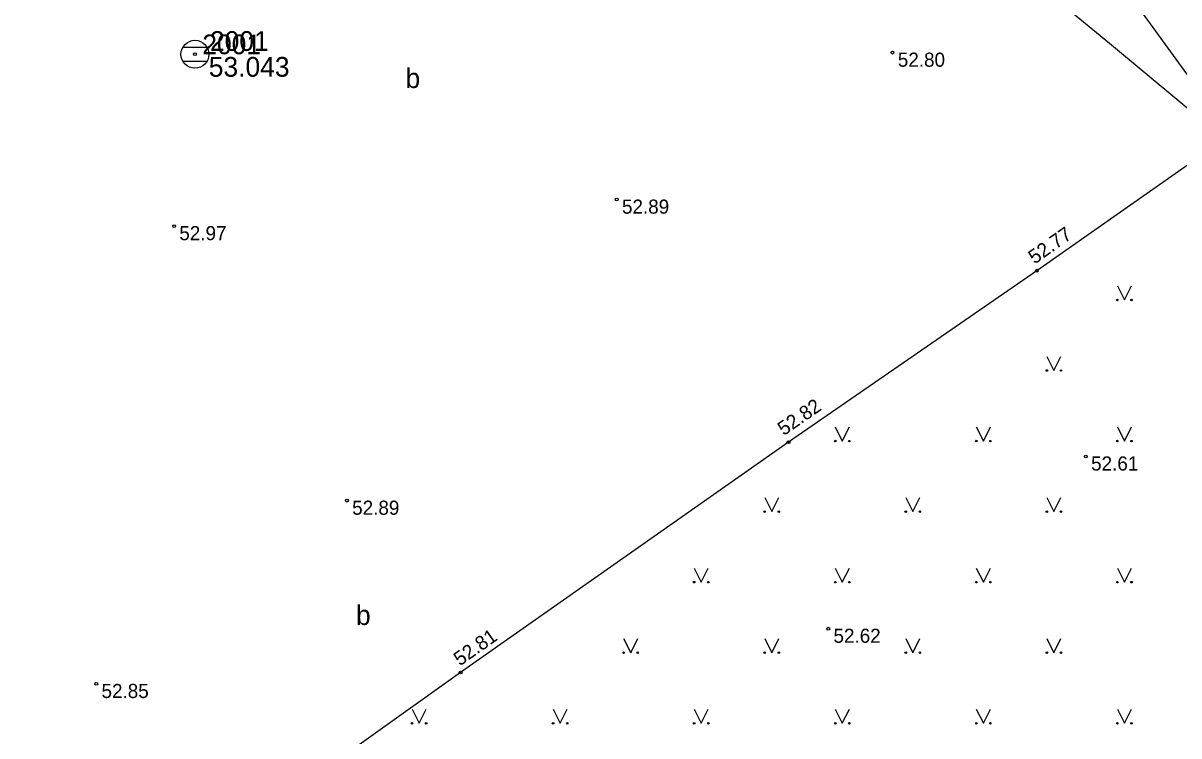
# Model space of a CAD drawing. Extents: x 619806 to 620082, y 405176 to 405386.
# Drawn here: x 619968.46 to 620009.43, y 405267.05 to 405292.31 of the extents above; entities that cross this region are included whole.
import ezdxf

# ---------------------------------------------------------------- set-up
doc = ezdxf.new("R2010")
doc.units = 0
for name, color, linetype in [('CELI_CMAL_####_####_#', 7, 'Continuous'), ('CELI_CSEG_####_TKST_#', 7, 'Continuous'), ('GEOD_ELEM_####_####_#', 7, 'Continuous'), ('GEOD_ELEM_####_TKST_#', 7, 'Continuous'), ('RELJ_AATZ_####_TKST_#', 7, 'Continuous'), ('RELJ_ELEM_####_####_#', 7, 'Continuous'), ('SAKT_VADP_KABE_####_#', 7, 'Continuous'), ('TERT_ELEM_####_####_#', 7, 'Continuous'), ('UDTK_VADP_UDEN_####_#', 7, 'Continuous')]:
    doc.layers.add(name, color=color, linetype=linetype)

msp = doc.modelspace()

# ---------------------------------------------------------------- linework, layer by layer
at = {"layer": 'CELI_CMAL_####_####_#'}
msp.add_lwpolyline([(620044.255, 405272.554), (620043.092, 405273.429), (620033.269, 405279.026), (620025.28, 405283.562), (620015.248, 405289.312), (620013.524, 405289.938), (620004.396, 405283.537), (619995.598, 405277.461), (619983.971, 405269.299), (619977.275, 405264.531), (619978.155, 405255.368), (619978.832, 405249.941), (619981.369, 405226.774)], dxfattribs=at)
at = {"layer": 'GEOD_ELEM_####_####_#'}
for p, q in [((619974.126, 405291.454), (619974.984, 405291.454)), ((619974.126, 405291.454), (619974.984, 405291.454)), ((619974.126, 405290.959), (619974.984, 405290.959)), ((619974.126, 405290.959), (619974.984, 405290.959))]:
    msp.add_line(p, q, dxfattribs=at)
for radius in [0.495, 0.495, 0.05, 0.05]:
    msp.add_circle((619974.555, 405291.207), radius, dxfattribs=at)
at = {"layer": 'RELJ_ELEM_####_####_#'}
for centre in [(619999.282, 405291.265), (619989.505, 405286.058), (619973.816, 405285.118), (620004.396, 405283.537), (619995.598, 405277.461), (620006.133, 405276.956), (619979.942, 405275.389), (619997.002, 405270.851), (619971.058, 405268.895), (619983.971, 405269.299)]:
    msp.add_circle(centre, 0.05, dxfattribs=at)
at = {"layer": 'SAKT_VADP_KABE_####_#'}
msp.add_lwpolyline([(619935.629, 405357.201), (619939.538, 405347.363), (619973.032, 405319.457), (620006.975, 405291.595), (620036.262, 405267.248), (620043.553, 405261.241)], dxfattribs=at)
at = {"layer": 'TERT_ELEM_####_####_#'}
for p, q in [((620007.25, 405283), (620007.5, 405282.5)), ((620007.5, 405282.5), (620007.75, 405283)), ((620004.75, 405280.5), (620005, 405280)), ((620005, 405280), (620005.25, 405280.5)), ((619997.25, 405278), (619997.5, 405277.5)), ((619997.5, 405277.5), (619997.75, 405278)), ((620002.25, 405278), (620002.5, 405277.5)), ((620002.5, 405277.5), (620002.75, 405278)), ((620007.25, 405278), (620007.5, 405277.5)), ((620007.5, 405277.5), (620007.75, 405278)), ((619994.75, 405275.5), (619995, 405275)), ((619995, 405275), (619995.25, 405275.5)), ((619999.75, 405275.5), (620000, 405275)), ((620000, 405275), (620000.25, 405275.5)), ((620004.75, 405275.5), (620005, 405275)), ((620005, 405275), (620005.25, 405275.5)), ((619992.25, 405273), (619992.5, 405272.5)), ((619992.5, 405272.5), (619992.75, 405273)), ((619997.25, 405273), (619997.5, 405272.5)), ((619997.5, 405272.5), (619997.75, 405273)), ((620002.25, 405273), (620002.5, 405272.5)), ((620002.5, 405272.5), (620002.75, 405273)), ((620007.25, 405273), (620007.5, 405272.5)), ((620007.5, 405272.5), (620007.75, 405273)), ((619989.75, 405270.5), (619990, 405270)), ((619990, 405270), (619990.25, 405270.5)), ((619994.75, 405270.5), (619995, 405270)), ((619995, 405270), (619995.25, 405270.5)), ((619999.75, 405270.5), (620000, 405270)), ((620000, 405270), (620000.25, 405270.5)), ((620004.75, 405270.5), (620005, 405270)), ((620005, 405270), (620005.25, 405270.5)), ((619982.25, 405268), (619982.5, 405267.5)), ((619982.5, 405267.5), (619982.75, 405268)), ((619987.25, 405268), (619987.5, 405267.5)), ((619987.5, 405267.5), (619987.75, 405268)), ((619992.25, 405268), (619992.5, 405267.5)), ((619992.5, 405267.5), (619992.75, 405268)), ((619997.25, 405268), (619997.5, 405267.5)), ((619997.5, 405267.5), (619997.75, 405268)), ((620002.25, 405268), (620002.5, 405267.5)), ((620002.5, 405267.5), (620002.75, 405268)), ((620007.25, 405268), (620007.5, 405267.5)), ((620007.5, 405267.5), (620007.75, 405268))]:
    msp.add_line(p, q, dxfattribs=at)
for centre, radius in [((620007.25, 405282.5), 0.028), ((620007.75, 405282.5), 0.0263), ((620004.75, 405280), 0.028), ((620005.25, 405280), 0.0263), ((619997.25, 405277.5), 0.028), ((619997.75, 405277.5), 0.0263), ((620002.25, 405277.5), 0.028), ((620002.75, 405277.5), 0.0263), ((620007.25, 405277.5), 0.028), ((620007.75, 405277.5), 0.0263), ((619994.75, 405275), 0.028), ((619995.25, 405275), 0.0263), ((619999.75, 405275), 0.028), ((620000.25, 405275), 0.0263), ((620004.75, 405275), 0.028), ((620005.25, 405275), 0.0263), ((619992.25, 405272.5), 0.028), ((619992.75, 405272.5), 0.0263), ((619997.25, 405272.5), 0.028), ((619997.75, 405272.5), 0.0263), ((620002.25, 405272.5), 0.028), ((620002.75, 405272.5), 0.0263), ((620007.25, 405272.5), 0.028), ((620007.75, 405272.5), 0.0263), ((619989.75, 405270), 0.028), ((619990.25, 405270), 0.0263), ((619994.75, 405270), 0.028), ((619995.25, 405270), 0.0263), ((619999.75, 405270), 0.028), ((620000.25, 405270), 0.0263), ((620004.75, 405270), 0.028), ((620005.25, 405270), 0.0263), ((619982.25, 405267.5), 0.028), ((619982.75, 405267.5), 0.0263), ((619987.25, 405267.5), 0.028), ((619987.75, 405267.5), 0.0263), ((619992.25, 405267.5), 0.028), ((619992.75, 405267.5), 0.0263), ((619997.25, 405267.5), 0.028), ((619997.75, 405267.5), 0.0263), ((620002.25, 405267.5), 0.028), ((620002.75, 405267.5), 0.0263), ((620007.25, 405267.5), 0.028), ((620007.75, 405267.5), 0.0263)]:
    msp.add_circle(centre, radius, dxfattribs=at)
at = {"layer": 'UDTK_VADP_UDEN_####_#'}
msp.add_lwpolyline([(620006.936, 405294.332), (620021.003, 405274.963), (620032.468, 405267.412)], dxfattribs=at)

# ---------------------------------------------------------------- texts
at = {"layer": 'CELI_CSEG_####_TKST_#'}
for p in [(619982.018, 405290.01), (619980.265, 405270.983)]:
    msp.add_text('b', height=0.7, dxfattribs=at).set_placement(p)
at = {"layer": 'GEOD_ELEM_####_TKST_#'}
for s, p in [(' 2001', (619974.555, 405291.207)), (' 2001', (619974.827, 405291.325)), (' 53.043', (619974.785, 405290.411))]:
    msp.add_text(s, height=0.7, dxfattribs=at).set_placement(p)
at = {"layer": 'RELJ_AATZ_####_TKST_#'}
for s, p in [(' 52.80', (619999.282, 405290.765)), (' 52.89', (619989.505, 405285.558)), (' 52.97', (619973.816, 405284.618)), (' 52.61', (620006.133, 405276.456)), (' 52.89', (619979.942, 405274.889)), (' 52.62', (619997.002, 405270.351)), (' 52.85', (619971.058, 405268.395))]:
    msp.add_text(s, height=0.5, dxfattribs=at).set_placement(p)
for s, rotation, p in [(' 52.77', 35.04, (620004.164, 405283.647)), (' 52.82', 34.6294, (619995.273, 405277.569)), (' 52.81', 35.0683, (619983.794, 405269.406))]:
    msp.add_text(s, height=0.5, rotation=rotation, dxfattribs=at).set_placement(p)

doc.saveas('drawing.dxf')
